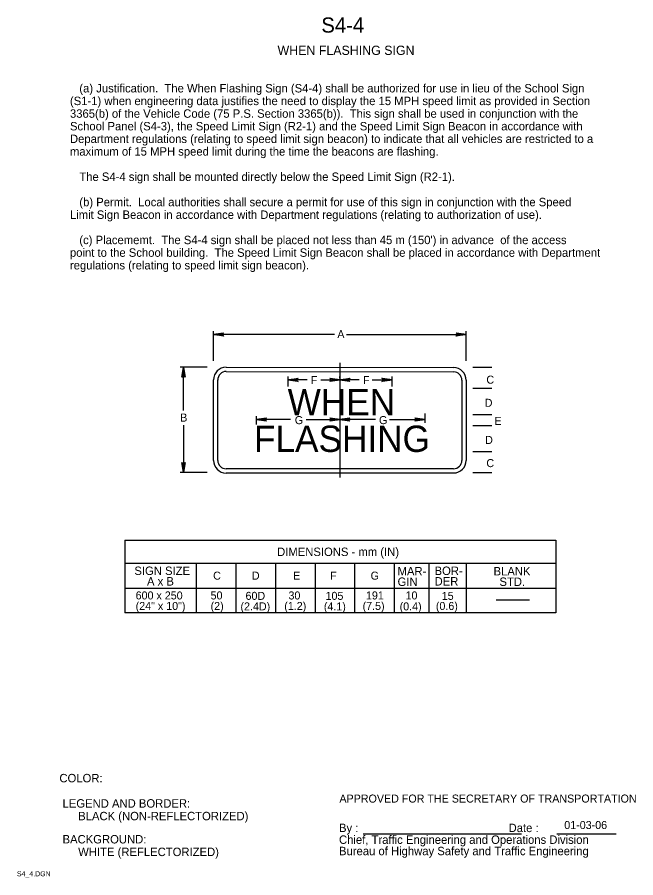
# Model space of a CAD drawing. Extents: x 0.013 to 0.196, y 0.004 to 0.259.
import ezdxf

# ---------------------------------------------------------------- set-up
doc = ezdxf.new("R2010")
doc.units = 0
for name, color, linetype in [('1', 7, 'Continuous'), ('2', 7, 'Continuous'), ('3', 7, 'Continuous'), ('4', 7, 'Continuous')]:
    doc.layers.add(name, color=color, linetype=linetype)

# ---------------------------------------------------------------- blocks, each defined once
blk = doc.blocks.new('RARROW')
at = {"layer": '3'}
for p, q in [((-2.156, 0.285), (-2.2665, 0.384625)), ((-2.2665, 0.384625), (0, 0)), ((0, 0), (-2.2665, -0.379125)), ((-2.156, 0.285), (-2.075625, 0.12075)), ((0, 0), (-2.156, 0.285)), ((-2.14975, -0.2705), (0, 0)), ((-2.075625, 0.12075), (0, 0)), ((0, 0), (-2.074, -0.108)), ((-2.2665, -0.379125), (-2.14975, -0.2705)), ((-2.074, -0.108), (-2.14975, -0.2705))]:
    blk.add_line(p, q, dxfattribs=at)

msp = doc.modelspace()

# ---------------------------------------------------------------- linework, layer by layer
at = {"layer": '1'}
for p, q in [((0.1085, 0.15663), (0.1085, 0.12262)), ((0.11544, 0.01695), (0.16242, 0.01695)), ((0.17295, 0.01695), (0.19056, 0.01695))]:
    msp.add_line(p, q, dxfattribs=at)
at = {"layer": '3'}
for p, q in [((0.071, 0.15725), (0.071, 0.16612)), ((0.146, 0.15725), (0.146, 0.16612)), ((0.10695, 0.16512), (0.071, 0.16512)), ((0.11052, 0.16512), (0.146, 0.16512)), ((0.0691, 0.15538), (0.06112, 0.15538)), ((0.06212, 0.14255), (0.06212, 0.15538)), ((0.07475, 0.15538), (0.14225, 0.15525)), ((0.07475, 0.15413), (0.14225, 0.154)), ((0.148, 0.15538), (0.15363, 0.15538)), ((0.071, 0.12775), (0.071, 0.15162)), ((0.07225, 0.12775), (0.07225, 0.15162)), ((0.09312, 0.14963), (0.09312, 0.15263)), ((0.09875, 0.15162), (0.09312, 0.15162)), ((0.10288, 0.15162), (0.1085, 0.15162)), ((0.1085, 0.15213), (0.1085, 0.15263)), ((0.11425, 0.15162), (0.1085, 0.15162)), ((0.11813, 0.15162), (0.124, 0.15162)), ((0.124, 0.14963), (0.124, 0.15263)), ((0.14475, 0.1515), (0.14475, 0.12775)), ((0.146, 0.1515), (0.146, 0.12775)), ((0.148, 0.14913), (0.15363, 0.14913)), ((0.08375, 0.13837), (0.08375, 0.14088)), ((0.13375, 0.14163), (0.13375, 0.13887)), ((0.148, 0.14138), (0.15363, 0.14138)), ((0.06212, 0.13823), (0.06212, 0.12412)), ((0.09388, 0.13987), (0.08375, 0.13987)), ((0.0985, 0.13987), (0.1085, 0.13987)), ((0.11913, 0.13987), (0.1085, 0.13987)), ((0.12325, 0.13987), (0.13375, 0.13987)), ((0.148, 0.13812), (0.15363, 0.13812)), ((0.148, 0.13037), (0.15363, 0.13037)), ((0.14225, 0.12525), (0.07475, 0.12525)), ((0.0691, 0.12412), (0.06112, 0.12412)), ((0.14225, 0.124), (0.07475, 0.124)), ((0.148, 0.12412), (0.15363, 0.12412)), ((0.04462, 0.10412), (0.17263, 0.10412)), ((0.04462, 0.10412), (0.04462, 0.0825)), ((0.17263, 0.10412), (0.17263, 0.0825)), ((0.17263, 0.09713), (0.04462, 0.09713)), ((0.06588, 0.09713), (0.06588, 0.0825)), ((0.07762, 0.09713), (0.07762, 0.0825)), ((0.08937, 0.09713), (0.08937, 0.0825)), ((0.10113, 0.09713), (0.10113, 0.0825)), ((0.11288, 0.09713), (0.11288, 0.0825)), ((0.12462, 0.09713), (0.12462, 0.0825)), ((0.12462, 0.09713), (0.12462, 0.08388)), ((0.13487, 0.09713), (0.13487, 0.0825)), ((0.146, 0.097), (0.146, 0.0825)), ((0.17263, 0.08975), (0.04462, 0.08975)), ((0.15488, 0.08638), (0.16475, 0.08638)), ((0.17263, 0.0825), (0.04462, 0.0825))]:
    msp.add_line(p, q, dxfattribs=at)
for centre, radius, start, end in [((0.07475, 0.15162), 0.00375, 90, 180), ((0.07478, 0.15159), 0.00253, 90.5918, 180.5918), ((0.14226, 0.15152), 0.00374, 359.7012, 89.7012), ((0.14226, 0.15152), 0.00249, 359.5514, 89.5514), ((0.07475, 0.12775), 0.00375, 180, 270), ((0.07475, 0.12775), 0.0025, 180, 270), ((0.14227, 0.12774), 0.00373, 270.1007, 0.1007), ((0.14227, 0.12774), 0.00248, 270.1515, 0.1515)]:
    msp.add_arc(centre, radius, start, end, dxfattribs=at)

# ---------------------------------------------------------------- block references
at = {"layer": '3', "xscale": 0.0013236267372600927, "yscale": 0.001309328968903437}
for p, rotation in [((0.071, 0.16512), 180), ((0.06212, 0.15538), 90), ((0.09312, 0.15162), 180), ((0.1085, 0.15162), 180), ((0.08375, 0.13987), 180), ((0.1085, 0.13987), 180), ((0.06212, 0.12412), -90)]:
    msp.add_blockref('RARROW', p, dxfattribs=dict(at, rotation=rotation))
for p in [(0.146, 0.16512), (0.1085, 0.15162), (0.124, 0.15162), (0.1085, 0.13987), (0.13375, 0.13987)]:
    msp.add_blockref('RARROW', p, dxfattribs=at)

# ---------------------------------------------------------------- texts
at = {"layer": '1'}
for s, height, p in [('S4-4', 0.0045, (0.103, 0.25462)), ('WHEN FLASHING SIGN', 0.0027503, (0.09, 0.248)), ('COLOR:', 0.0025, (0.02525, 0.03225)), ('APPROVED FOR THE SECRETARY OF TRANSPORTATION', 0.0023752, (0.10837, 0.02625)), (' LEGEND AND BORDER:', 0.0024998, (0.02525, 0.02475)), ('      BLACK (NON-REFLECTORIZED)', 0.0024998, (0.02525, 0.021)), ('By :                                                Date :', 0.0024998, (0.10825, 0.0175)), (' BACKGROUND:', 0.0024998, (0.02525, 0.01413)), ('Chief, Traffic Engineering and Operations Division', 0.0024998, (0.10825, 0.014)), ('      WHITE (REFLECTORIZED)', 0.0024998, (0.02525, 0.01038)), ('Bureau of Highway Safety and Traffic Engineering', 0.0024998, (0.10825, 0.01063)), ('S4_4.DGN', 0.0015, (0.01263, 0.00438))]:
    msp.add_text(s, height=height, dxfattribs=at).set_placement(p)
at = {"layer": '2'}
for s, height, p in [('   (a) Justification.  The When Flashing Sign (S4-4) shall be authorized for use in lieu of the School Sign', 0.00249975, (0.02838, 0.23688)), ('(S1-1) when engineering data justifies the need to display the 15 MPH speed limit as provided in Section', 0.00249975, (0.02838, 0.23312)), ('3365(b) of the Vehicle Code (75 P.S. Section 3365(b)).  This sign shall be used in conjunction with the', 0.00249975, (0.02838, 0.22937)), ('School Panel (S4-3), the Speed Limit Sign (R2-1) and the Speed Limit Sign Beacon in accordance with', 0.0024998, (0.02838, 0.22562)), ('Department regulations (relating to speed limit sign beacon) to indicate that all vehicles are restricted to a ', 0.00249975, (0.02838, 0.22188)), ('maximum of 15 MPH speed limit during the time the beacons are flashing. ', 0.0024998, (0.02838, 0.21813)), ('   The S4-4 sign shall be mounted directly below the Speed Limit Sign (R2-1).', 0.0024998, (0.02838, 0.21063)), ('   (b) Permit.  Local authorities shall secure a permit for use of this sign in conjunction with the Speed', 0.00249975, (0.02838, 0.20312)), ('Limit Sign Beacon in accordance with Department regulations (relating to authorization of use).', 0.0024998, (0.02838, 0.19937)), ("   (c) Placememt.  The S4-4 sign shall be placed not less than 45 m (150') in advance  of the access", 0.0024998, (0.02838, 0.19188)), ('point to the School building.  The Speed Limit Sign Beacon shall be placed in accordance with Department', 0.00249975, (0.02838, 0.18813)), ('regulations (relating to speed limit sign beacon).', 0.0024998, (0.02838, 0.18438))]:
    msp.add_text(s, height=height, dxfattribs=at).set_placement(p)
at = {"layer": '3'}
for s, height, p in [('A', 0.00238, (0.10775, 0.164)), ('F', 0.00238, (0.09988, 0.15038)), ('F', 0.00238, (0.11538, 0.15038)), ('C', 0.00238, (0.152, 0.1505)), ('WHEN', 0.007812, (0.093, 0.14113)), ('D', 0.00238, (0.1515, 0.14363)), ('B', 0.00238, (0.06112, 0.13925)), ('G', 0.00238, (0.09513, 0.1385)), ('G', 0.00238, (0.12012, 0.1385)), ('E', 0.00238, (0.15438, 0.13825)), ('FLASHING', 0.007812, (0.083, 0.13025)), ('D', 0.00238, (0.15162, 0.13262)), ('C', 0.00238, (0.152, 0.12575)), ('DIMENSIONS - mm (IN)', 0.0024998, (0.08987, 0.09938)), ('SIGN SIZE', 0.0025, (0.0475, 0.09375)), ('C', 0.00238, (0.07088, 0.09237)), ('D', 0.00238, (0.08238, 0.09237)), ('E', 0.00238, (0.09463, 0.09237)), ('F', 0.00238, (0.10562, 0.09237)), ('G', 0.00238, (0.11763, 0.09237)), ('MAR-', 0.0025, (0.12563, 0.09362)), ('BOR-', 0.0025, (0.13662, 0.09375)), ('BLANK', 0.0025, (0.15413, 0.09362)), ('A x B', 0.0025, (0.05125, 0.09062)), ('GIN', 0.0025, (0.12563, 0.0905)), ('DER', 0.0025, (0.13662, 0.09062)), ('STD.', 0.0025, (0.15588, 0.0905)), ('600 x 250', 0.002375, (0.04788, 0.0865)), ('50', 0.002375, (0.07013, 0.0865)), ('60D', 0.002375, (0.0805, 0.08638)), ('30', 0.002375, (0.09325, 0.0865)), ('105', 0.002375, (0.10425, 0.08638)), ('191', 0.002375, (0.11625, 0.0865)), ('10', 0.002375, (0.128, 0.0865)), ('15', 0.002375, (0.13875, 0.08638)), ('(24" x 10")', 0.0023752, (0.04788, 0.08338)), ('(2)', 0.002375, (0.07013, 0.08338)), ('(2.4D)', 0.002375, (0.079, 0.08325)), ('(1.2)', 0.002375, (0.092, 0.08338)), ('(4.1)', 0.002375, (0.10375, 0.08325)), ('(7.5)', 0.002375, (0.11525, 0.08338)), ('(0.4)', 0.002375, (0.12625, 0.08325)), ('(0.6)', 0.002375, (0.137, 0.08338))]:
    msp.add_text(s, height=height, dxfattribs=at).set_placement(p)
at = {"layer": '4'}
msp.add_text('01-03-06', height=0.002375, dxfattribs=at).set_placement((0.17512, 0.0184))

doc.saveas('drawing.dxf')
